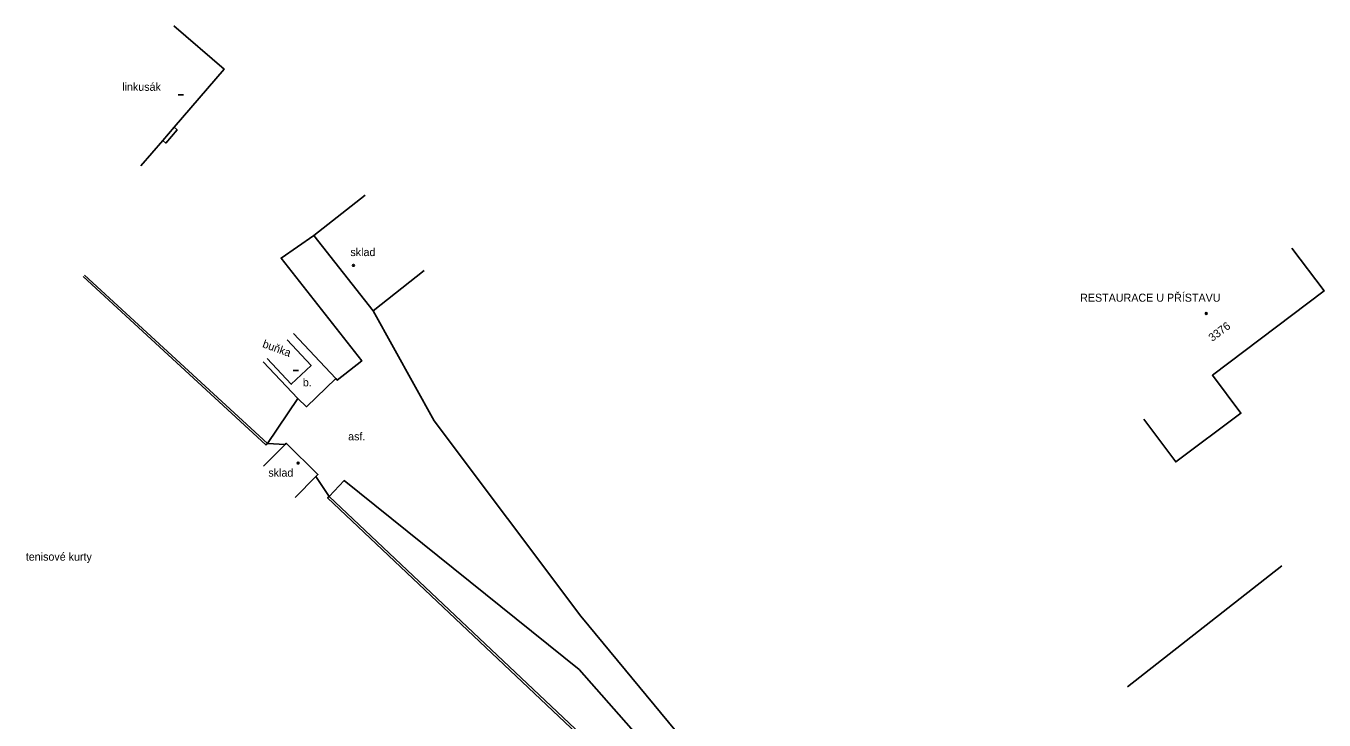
# Model space of a CAD drawing. Extents: x -584400 to -581602, y -1210894 to -1208793.
# Drawn here: x -583220.2 to -583098.6, y -1210188.6 to -1210123.7 of the extents above; entities that cross this region are included whole.
import ezdxf

# ---------------------------------------------------------------- set-up
doc = ezdxf.new("R2010")
doc.units = 0
for name, color, linetype in [('BUDOVY_MĚŘ', 7, 'Continuous'), ('POMOC_POPIS', 7, 'Continuous'), ('ROZHRANÍ_PLOCH', 7, 'Continuous'), ('ZN_BUDOV', 7, 'Continuous'), ('ZN_DOPLŇKOVÉ', 7, 'Continuous'), ('Č_POPIS_EVID', 7, 'Continuous')]:
    doc.layers.add(name, color=color, linetype=linetype)

msp = doc.modelspace()

# ---------------------------------------------------------------- linework, layer by layer
at = {"layer": 'BUDOVY_MĚŘ'}
for points in [[(-583206.39, -1210123.65), (-583201.69, -1210127.68), (-583206.37, -1210133.13), (-583207.43, -1210134.37), (-583209.47, -1210136.74)], [(-583188.47, -1210139.49), (-583193.27, -1210143.27), (-583187.73, -1210150.31), (-583182.93, -1210146.53)], [(-583101.65, -1210144.46), (-583098.64, -1210148.45), (-583109.1, -1210156.34), (-583106.43, -1210159.9), (-583112.53, -1210164.46), (-583115.53, -1210160.46)], [(-583197.66, -1210154.78), (-583195.4, -1210157.18), (-583193.53, -1210155.42), (-583195.79, -1210153.02)], [(-583197.98, -1210164.86), (-583195.97, -1210162.82), (-583195.86, -1210162.71), (-583192.9, -1210165.63), (-583193.09, -1210165.83), (-583195.02, -1210167.78)]]:
    msp.add_lwpolyline(points, dxfattribs=at)
at = {"layer": 'ROZHRANÍ_PLOCH'}
for points in [[(-583193.27, -1210143.27), (-583196.35, -1210145.38), (-583188.79, -1210155), (-583191.09, -1210156.81), (-583191.22, -1210156.65)], [(-583139.31, -1210213.9), (-583144.88, -1210207.78), (-583156.63, -1210192.98), (-583168.26, -1210178.91), (-583182.01, -1210160.6), (-583187.73, -1210150.31)], [(-583195.18, -1210152.44), (-583191.22, -1210156.65)], [(-583198.01, -1210155.1), (-583194.79, -1210158.52)], [(-583194.79, -1210158.52), (-583193.95, -1210159.3), (-583191.22, -1210156.65)], [(-583197.63, -1210162.72), (-583194.79, -1210158.52)], [(-583175.27, -1210249.99), (-583174.07, -1210243.82), (-583168.4, -1210234.36), (-583165.62, -1210231.13), (-583162.31, -1210228.01), (-583148.94, -1210216.93), (-583148.19, -1210214.96), (-583147.83, -1210212.88), (-583147.86, -1210210.78), (-583148.3, -1210208.71), (-583148.39, -1210208.42), (-583157.51, -1210196.23), (-583168.41, -1210183.89), (-583190.44, -1210166.21), (-583191.85, -1210167.68)]]:
    msp.add_lwpolyline(points, dxfattribs=at)
at = {"layer": 'ZN_BUDOV'}
for p, q in [((-583205.98, -1210130.1), (-583205.48, -1210130.1)), ((-583195.2, -1210155.9), (-583194.7, -1210155.9))]:
    msp.add_line(p, q, dxfattribs=at)
for centre in [(-583189.57, -1210146.06), (-583109.67, -1210150.56), (-583194.75, -1210164.56)]:
    msp.add_circle(centre, 0.0875, dxfattribs=at)
at = {"layer": 'ZN_DOPLŇKOVÉ'}
for points in [[(-583206.37, -1210133.13), (-583206.08, -1210133.37), (-583207.15, -1210134.61), (-583207.43, -1210134.37)], [(-583214.9, -1210147.11), (-583197.77, -1210162.87), (-583197.63, -1210162.72)], [(-583197.63, -1210162.72), (-583214.77, -1210146.97)], [(-583195.97, -1210162.82), (-583197.63, -1210162.72)], [(-583191.85, -1210167.68), (-583193.09, -1210165.83)], [(-583179.34, -1210236.02), (-583174.55, -1210240.41), (-583151.48, -1210215.22), (-583148.84, -1210211.52), (-583149.43, -1210208.7), (-583152.64, -1210204.97), (-583191.99, -1210167.83), (-583191.85, -1210167.68)], [(-583174.54, -1210240.69), (-583151.32, -1210215.35), (-583148.63, -1210211.57), (-583149.24, -1210208.61), (-583152.49, -1210204.83), (-583191.85, -1210167.68)], [(-583102.58, -1210174.2), (-583117.04, -1210185.51)]]:
    msp.add_lwpolyline(points, dxfattribs=at)

# ---------------------------------------------------------------- texts
at = {"layer": 'POMOC_POPIS'}
for s, p in [('linkusák', (-583211.23, -1210129.72)), ('sklad', (-583189.85, -1210145.19)), ('RESTAURACE U PŘÍSTAVU', (-583121.49, -1210149.46)), ('b.', (-583194.31, -1210157.38)), ('asf.', (-583190.07, -1210162.44)), ('sklad', (-583197.54, -1210165.84)), ('tenisové kurty', (-583220.26, -1210173.7))]:
    msp.add_text(s, height=0.75, dxfattribs=at).set_placement(p)
msp.add_text('buňka', height=0.75, rotation=340.0383, dxfattribs=at).set_placement((-583198.15, -1210153.71))
at = {"layer": 'Č_POPIS_EVID'}
msp.add_text('3376', height=0.75, rotation=37.0273, dxfattribs=at).set_placement((-583109.11, -1210153.23))

doc.saveas('drawing.dxf')
